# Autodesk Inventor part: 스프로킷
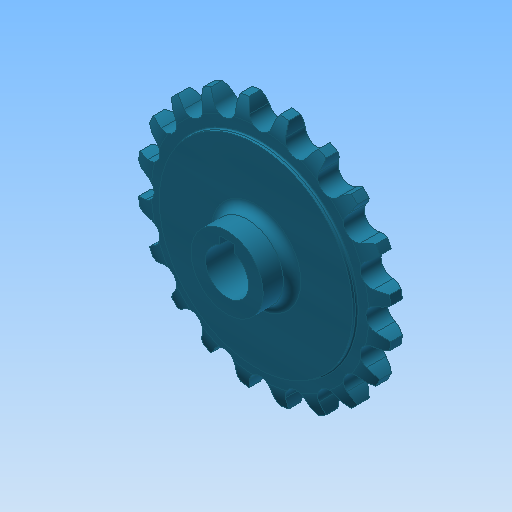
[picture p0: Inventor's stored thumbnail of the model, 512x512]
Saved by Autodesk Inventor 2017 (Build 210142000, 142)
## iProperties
Created: 2016-03
Part Number: 스프로킷
Material: 강철, 탄소
Document SubType Name: Modeling
Designer: mduedu
Density: 7.87 g/cm^3
Mass: 301.818 g
Surface Area: 124.882 cm^2
Volume: 38.3505 cm^3
Appearance: 터키옥색
Author: mduedu
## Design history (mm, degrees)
sketch "스케치1"
  geometry: L1 (0, 5)-(33.5, 5); L2 (33.5, 5)-(33.5, 4.1); L3 (34, 3.6)-(37.625, 3.6); L4 (44, 2)-(44, 0); L5 (44, 0)-(0, 0); L6 (0, 0)-(0, 5); L7 (0, -5)-(33.5, -5); L8 (33.5, -5)-(33.5, -4.1); L9 (34, -3.6)-(37.625, -3.6); L10 (44, -2)-(44, 0); L11 (0, 0)-(0, -5); A1 r 13.5 centre (37.625, -9.9) between (44, 2) and (37.625, 3.6); A2 r 13.5 centre (37.625, 9.9) between (37.625, -3.6) and (44, -2); A3 r 0.5 centre (34, 4.1) between (33.5, 4.1) and (34, 3.6); A4 r 0.5 centre (34, -4.1) between (34, -3.6) and (33.5, -4.1); 2 further points
  constraints: 22 end point, 8 point on circle, 6 symmetric about line, 5 tangent, 4 centre point, 4 parallel, 4 point on line, 1 equal radius, 1 horizontal, 1 perpendicular, 1 other
  dimensions: "d0" = 88 diameter of L4 L6; "d2" = 67 diameter of L2 L6; "d3" = 1.6 vertical distance of L4.start L3.end; "d4" = 3.6 distance from line of L4.end L3; "d5" = 5 distance between parallel lines of L5 L1; "d6" = 13.5 radius of A1; "d15" = 0.5 radius of A3
revolve "회전1" sketch "스케치1" stored, may be unused: angle "d7" = 90 deg
sketch "스케치2" dims "d8" = 73.24, "d11" = 88
  geometry: L1 (0, 0)-(0, 36.62); A1 r 40.59 centre (0, 0) between (-16.315, 37.167) and (0, 40.59); A2 r 3.97 centre (0, 40.59) between (-3.885, 39.775) and (0, 36.62); A3 r 12.7 centre (-16.315, 37.167) between (-3.885, 39.775) and (-5.404, 43.667); A4 r 12.7 centre (16.315, 37.167) between (5.404, 43.667) and (3.885, 39.775); A5 r 3.97 centre (0, 40.59) between (0, 36.62) and (3.885, 39.775); A6 r 44 centre (0, 0) between (5.404, 43.667) and (-5.404, 43.667); 2 further points
  constraints: 12 point on circle, 6 centre point, 4 coincident, 3 symmetric about line, 2 end point, 1 point on line, 1 tangent, 1 vertical, 1 vertical alignment, 7 other
  dimensions: "d10" = 81.18 diameter of A1; "d12" = 12.7 radius of A3
extrude "돌출1" cut sketch "스케치2" stored distance "d13" = 10; taper "d14" = 0 deg
sketch "스케치3"
  geometry: C1 r 12.5 at (0, 0); 1 further point
  constraints: 1 centre point, 1 coincident
  dimensions: "d19" = 25 diameter of C1
extrude "돌출2" join sketch "스케치3" distance "d20" = 10; taper "d21" = 0 deg
fillet "모깎기1" dims "d22" = 3
sketch "스케치4"
  geometry: L1 (-2.5, 0)-(2.5, 0); L2 (2.5, 0)-(2.5, 9.8); L3 (2.5, 9.8)-(-2.5, 9.8); L4 (-2.5, 9.8)-(-2.5, 0); C1 r 7.5 at (0, 0); 2 further points
  constraints: 8 end point, 2 coincident, 2 parallel, 1 centre point, 1 horizontal, 1 midpoint, 1 perpendicular
  dimensions: "d23" = 15 diameter of C1; "d25" = 5 distance of L2.end L3.end; "d26" = 9.8 distance of L1.end L2.end
extrude "돌출3" cut sketch "스케치4" stored distance "d27" = 8; taper "d28" = 0 deg
node "솔리드1"
pattern_circular "원형 패턴1" dims angle "d17" = 360 deg
